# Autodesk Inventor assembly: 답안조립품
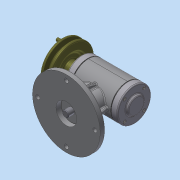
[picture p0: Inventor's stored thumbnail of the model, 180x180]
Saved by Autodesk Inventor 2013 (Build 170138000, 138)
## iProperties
Created: 2018-06
Part Number: 답안조립품
Document SubType Name: Assembly
Designer: dgall
Author: dgall
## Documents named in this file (18)
- C:\Users\dgall\Desktop\380607V1017\답안조립품.iam
- C:\Users\dgall\Desktop\380607V1017\본체.ipt
- C:\Users\dgall\Desktop\380607V1017\뒤커버.ipt
- C:\Users\dgall\Desktop\380607V1017\본체커버.ipt
- C:\Users\dgall\Desktop\380607V1017\오일 실 12 22 7.ipt
- 오일 실 12 22 7.ipt
- C:\Users\dgall\Desktop\380607V1017\키 4x4x18.ipt
- 키 4x4x18.ipt
- C:\Users\dgall\Desktop\380607V1017\편심축.ipt
- C:\Users\dgall\Desktop\380607V1017\베어링 6201.ipt
- C:\Users\dgall\Desktop\380607V1017\베어링 6202.ipt
- C:\Users\dgall\Desktop\380607V1017\앞커버.ipt
- C:\Users\dgall\Desktop\380607V1017\V-벨트풀리.ipt
- C:\Users\dgall\Desktop\380607V1017\멈춤나사 M3x8.ipt
- C:\Users\dgall\Desktop\380607V1017\개스킷.ipt
- C:\Users\dgall\Desktop\380607V1017\가변스프링.ipt
- C:\Users\dgall\Desktop\380607V1017\슬라이드.ipt
- C:\Users\dgall\Desktop\380607V1017\볼트 M3x0.5x8.ipt
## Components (4 placed, 3 different names)
1. V-벨트풀리:1
2. 개스킷:1
3. 개스킷:2
4. 가변스프링:1
